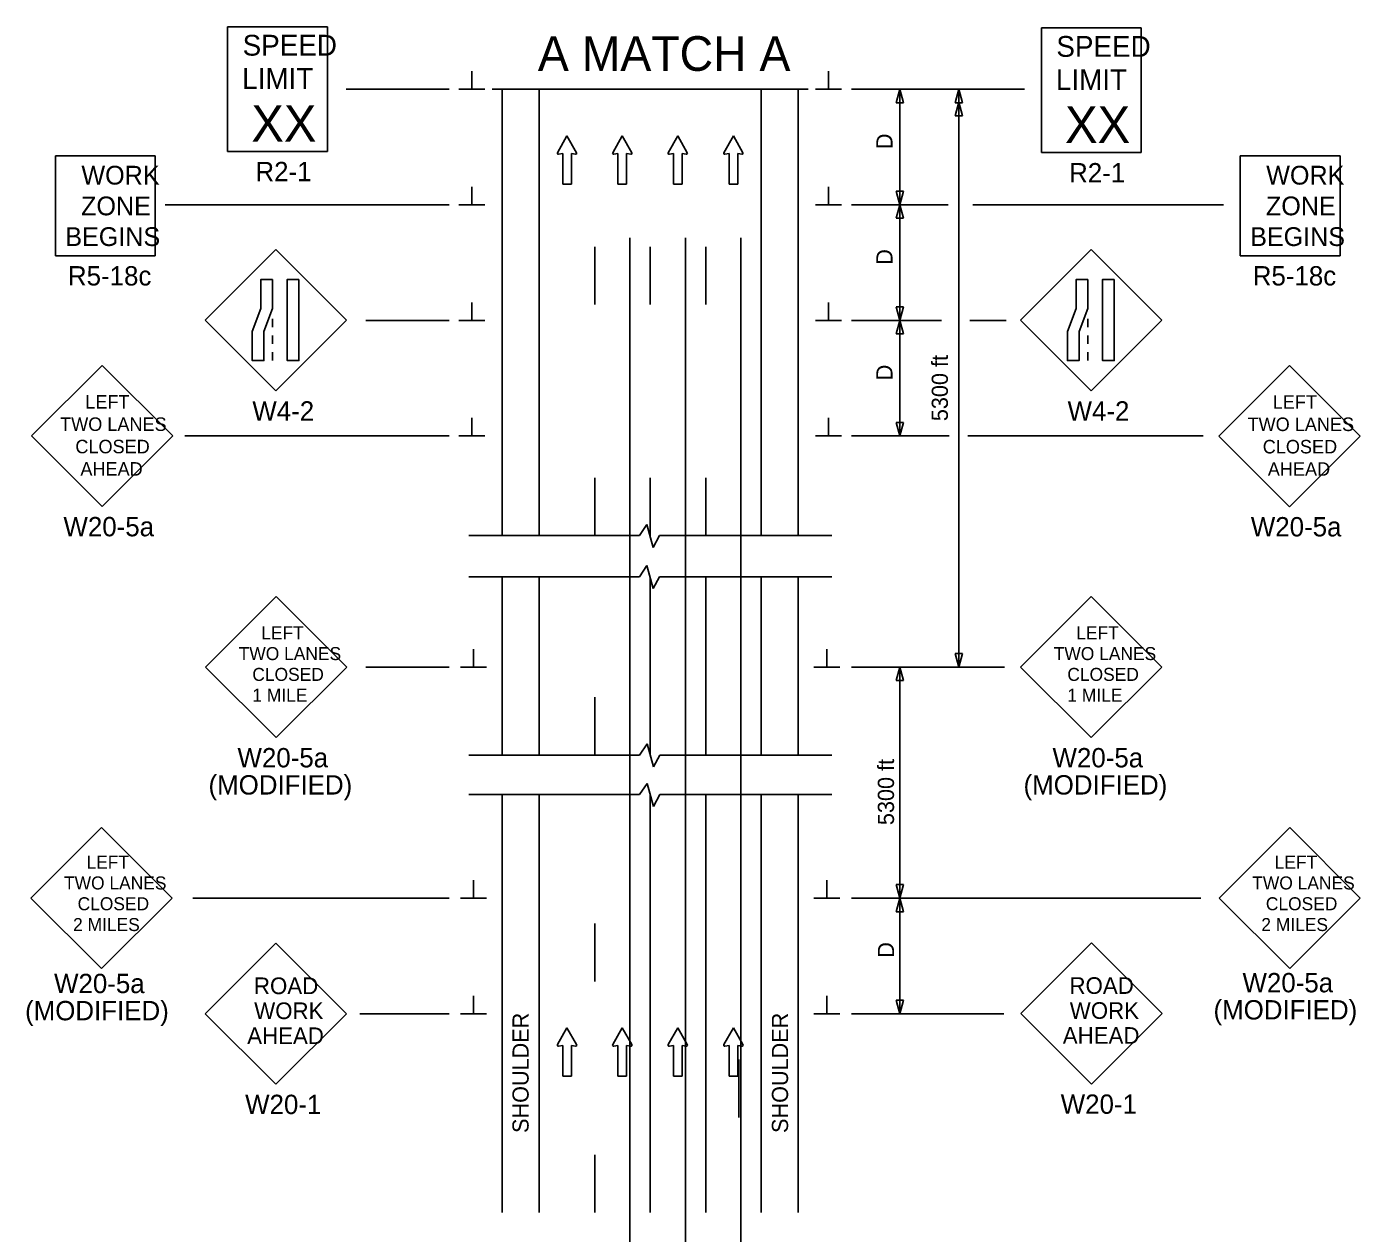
# Model space of a CAD drawing. Extents: x 16715 to 19504, y 7040 to 8495.
# Drawn here: x 17815 to 18392, y 7680 to 8202 of the extents above; entities that cross this region are included whole.
import ezdxf

# ---------------------------------------------------------------- set-up
doc = ezdxf.new("R2010")
doc.units = 0
for name, color, linetype in [('ALI_LEGAL_EX', 7, 'Continuous'), ('MT_SCRATCH_LEVEL_E', 7, 'Continuous'), ('PAVT_EDGE_EX', 7, 'Continuous'), ('TRAFFIC_SIGNS_PR', 7, 'Continuous'), ('TYPICAL_TEXT_DIMEN_PR', 7, 'Continuous')]:
    doc.layers.add(name, color=color, linetype=linetype)

msp = doc.modelspace()

# ---------------------------------------------------------------- linework, layer by layer
at = {"layer": 'ALI_LEGAL_EX'}
for p, q in [((18076.31, 7500.83), (18076.31, 8111.03)), ((18100.31, 7500.83), (18100.31, 8111.03)), ((18124.31, 7500.83), (18124.31, 8111.03)), ((18085.1, 7887.3), (18085.1, 7964.46)), ((18109.1, 7887.3), (18109.1, 7964.46)), ((18085.1, 7689.36), (18085.1, 7870.16)), ((18109.1, 7689.36), (18109.1, 7870.16))]:
    msp.add_line(p, q, dxfattribs=at)
for points in [[(18061.1, 8082.21), (18061.1, 8107.21)], [(18085.1, 8082.21), (18085.1, 8107.21)], [(18109.1, 8082.21), (18109.1, 8107.21)], [(18061.1, 7982.2), (18061.1, 8007.21)], [(18085.1, 7981.86), (18085.1, 8007.21)], [(18109.1, 7982.2), (18109.1, 8007.21)], [(18061.1, 7887.29), (18061.1, 7912.3)], [(18085.1, 7887.27), (18085.1, 7912.3)], [(18109.1, 7887.29), (18109.1, 7912.3)], [(18061.1, 7789.36), (18061.1, 7814.36)], [(18085.1, 7789.36), (18085.1, 7814.36)], [(18109.1, 7789.36), (18109.1, 7814.36)], [(18123.44, 7755.49), (18123.44, 7730.49)], [(18061.1, 7689.36), (18061.1, 7714.36)], [(18085.1, 7689.36), (18085.1, 7714.36)], [(18109.1, 7689.36), (18109.1, 7714.36)]]:
    msp.add_lwpolyline(points, dxfattribs=at)
at = {"layer": 'MT_SCRATCH_LEVEL_E'}
for p, q in [((18049.1, 8155.12), (18044.99, 8147.88)), ((18053.25, 8147.88), (18049.1, 8155.12)), ((18073.01, 8155.12), (18068.9, 8147.88)), ((18077.15, 8147.88), (18073.01, 8155.12)), ((18097.01, 8155.12), (18092.9, 8147.88)), ((18101.15, 8147.88), (18097.01, 8155.12)), ((18121.06, 8155.12), (18116.95, 8147.88)), ((18125.21, 8147.88), (18121.06, 8155.12)), ((18045.47, 8147.19), (18047.25, 8147.51)), ((18047.25, 8147.51), (18047.25, 8134.25)), ((18050.99, 8134.25), (18050.99, 8147.51)), ((18050.99, 8147.51), (18052.77, 8147.19)), ((18069.38, 8147.19), (18071.15, 8147.51)), ((18071.15, 8147.51), (18071.15, 8134.25)), ((18074.9, 8134.25), (18074.9, 8147.51)), ((18074.9, 8147.51), (18076.67, 8147.19)), ((18093.38, 8147.19), (18095.15, 8147.51)), ((18095.15, 8147.51), (18095.15, 8134.25)), ((18098.9, 8134.25), (18098.9, 8147.51)), ((18098.9, 8147.51), (18100.67, 8147.19)), ((18117.43, 8147.19), (18119.21, 8147.51)), ((18119.21, 8147.51), (18119.21, 8134.25)), ((18122.95, 8134.25), (18122.95, 8147.51)), ((18122.95, 8147.51), (18124.73, 8147.19)), ((18047.25, 8134.25), (18050.99, 8134.25)), ((18071.15, 8134.25), (18074.9, 8134.25)), ((18095.15, 8134.25), (18098.9, 8134.25)), ((18119.21, 8134.25), (18122.95, 8134.25)), ((18049.1, 7769.24), (18044.99, 7761.99)), ((18053.25, 7761.99), (18049.1, 7769.24)), ((18073.01, 7769.24), (18068.9, 7761.99)), ((18077.15, 7761.99), (18073.01, 7769.24)), ((18097.01, 7769.24), (18092.9, 7761.99)), ((18101.15, 7761.99), (18097.01, 7769.24)), ((18121.06, 7769.24), (18116.95, 7761.99)), ((18125.21, 7761.99), (18121.06, 7769.24)), ((18045.47, 7761.31), (18047.25, 7761.62)), ((18047.25, 7761.62), (18047.25, 7748.37)), ((18050.99, 7748.37), (18050.99, 7761.62)), ((18050.99, 7761.62), (18052.77, 7761.31)), ((18069.38, 7761.31), (18071.15, 7761.62)), ((18071.15, 7761.62), (18071.15, 7748.37)), ((18074.9, 7748.37), (18074.9, 7761.62)), ((18074.9, 7761.62), (18076.67, 7761.31)), ((18093.38, 7761.31), (18095.15, 7761.62)), ((18095.15, 7761.62), (18095.15, 7748.37)), ((18098.9, 7748.37), (18098.9, 7761.62)), ((18098.9, 7761.62), (18100.67, 7761.31)), ((18117.43, 7761.31), (18119.21, 7761.62)), ((18119.21, 7761.62), (18119.21, 7748.37)), ((18122.95, 7748.37), (18122.95, 7761.62)), ((18122.95, 7761.62), (18124.73, 7761.31)), ((18047.25, 7748.37), (18050.99, 7748.37)), ((18071.15, 7748.37), (18074.9, 7748.37)), ((18095.15, 7748.37), (18098.9, 7748.37)), ((18119.21, 7748.37), (18122.95, 7748.37))]:
    msp.add_line(p, q, dxfattribs=at)
for centre, start, end in [((18045.4, 8147.65), 150.42484, 279.96381), ((18052.84, 8147.65), 260.03619, 29.77312), ((18069.3, 8147.65), 150.42484, 279.96381), ((18076.74, 8147.65), 260.03619, 29.77312), ((18093.3, 8147.65), 150.42484, 279.96381), ((18100.74, 8147.65), 260.03619, 29.77312), ((18117.36, 8147.65), 150.42484, 279.96381), ((18124.8, 8147.65), 260.03619, 29.77312), ((18045.4, 7761.77), 150.42484, 279.96381), ((18052.84, 7761.77), 260.03619, 29.77312), ((18069.3, 7761.77), 150.42484, 279.96381), ((18076.74, 7761.77), 260.03619, 29.77312), ((18093.3, 7761.77), 150.42484, 279.96381), ((18100.74, 7761.77), 260.03619, 29.77312), ((18117.36, 7761.77), 150.42484, 279.96381), ((18124.8, 7761.77), 260.03619, 29.77312)]:
    msp.add_arc(centre, 0.463, start, end, dxfattribs=at)
at = {"layer": 'PAVT_EDGE_EX'}
for p, q in [((18021.1, 8175.36), (18021.1, 7982.2)), ((18037.1, 8175.36), (18037.1, 7982.2)), ((18133.1, 8175.36), (18133.1, 7982.2)), ((18149.1, 8175.36), (18149.1, 7982.2)), ((18021.1, 7964.45), (18021.1, 7887.29)), ((18037.1, 7964.46), (18037.1, 7887.29)), ((18133.1, 7964.45), (18133.1, 7887.29)), ((18149.1, 7964.45), (18149.1, 7887.29)), ((18021.1, 7870.15), (18021.1, 7689.36)), ((18037.1, 7870.15), (18037.1, 7689.36)), ((18133.1, 7870.15), (18133.1, 7689.36)), ((18149.1, 7870.15), (18149.1, 7689.36))]:
    msp.add_line(p, q, dxfattribs=at)
at = {"layer": 'TRAFFIC_SIGNS_PR'}
for p, q in [((17902.34, 8202.42), (17945.54, 8202.42)), ((17902.34, 8148.42), (17902.34, 8202.42)), ((17945.54, 8148.42), (17945.54, 8202.42)), ((18254.25, 8201.91), (18297.45, 8201.91)), ((18254.25, 8147.91), (18254.25, 8201.91)), ((18297.45, 8147.91), (18297.45, 8201.91)), ((17827.86, 8103.31), (17827.86, 8146.51)), ((17827.86, 8146.51), (17871.06, 8146.51)), ((17871.06, 8103.31), (17871.06, 8146.51)), ((17902.34, 8148.42), (17945.54, 8148.42)), ((18254.25, 8147.91), (18297.45, 8147.91)), ((18340.27, 8103.31), (18340.27, 8146.51)), ((18340.27, 8146.51), (18383.47, 8146.51)), ((18383.47, 8103.31), (18383.47, 8146.51)), ((17923.19, 8105.95), (17892.65, 8075.4)), ((17953.74, 8075.4), (17923.19, 8105.95)), ((18275.77, 8105.94), (18245.23, 8075.4)), ((18306.32, 8075.4), (18275.77, 8105.94)), ((17827.86, 8103.31), (17871.06, 8103.31)), ((18340.27, 8103.31), (18383.47, 8103.31)), ((17892.65, 8075.4), (17923.19, 8044.85)), ((17921.79, 8075.95), (17921.79, 8072.35)), ((17923.19, 8044.85), (17953.74, 8075.4)), ((18245.23, 8075.4), (18275.77, 8044.85)), ((18274.37, 8075.95), (18274.37, 8072.35)), ((18275.77, 8044.85), (18306.32, 8075.4)), ((17921.79, 8068.75), (17921.79, 8065.15)), ((18274.37, 8068.75), (18274.37, 8065.15)), ((17921.79, 8061.55), (17921.79, 8057.95)), ((18274.37, 8061.55), (18274.37, 8057.95)), ((17848.05, 8055.88), (17817.5, 8025.33)), ((17878.6, 8025.33), (17848.05, 8055.88)), ((18361.58, 8055.83), (18331.04, 8025.28)), ((18392.13, 8025.28), (18361.58, 8055.83)), ((17817.5, 8025.33), (17848.05, 7994.79)), ((17848.05, 7994.79), (17878.6, 8025.33)), ((18331.04, 8025.28), (18361.58, 7994.74)), ((18361.58, 7994.74), (18392.13, 8025.28)), ((17923.32, 7955.91), (17892.77, 7925.36)), ((17953.87, 7925.36), (17923.32, 7955.91)), ((18275.81, 7955.91), (18245.26, 7925.36)), ((18306.35, 7925.36), (18275.81, 7955.91)), ((17892.77, 7925.36), (17923.32, 7894.82)), ((17923.32, 7894.82), (17953.87, 7925.36)), ((18245.26, 7925.36), (18275.81, 7894.82)), ((18275.81, 7894.82), (18306.35, 7925.36)), ((17847.77, 7855.97), (17817.22, 7825.43)), ((17878.31, 7825.43), (17847.77, 7855.97)), ((18361.66, 7855.97), (18331.12, 7825.43)), ((18392.21, 7825.43), (18361.66, 7855.97)), ((17817.22, 7825.43), (17847.77, 7794.88)), ((17847.77, 7794.88), (17878.31, 7825.43)), ((18331.12, 7825.43), (18361.66, 7794.88)), ((18361.66, 7794.88), (18392.21, 7825.43)), ((17923.22, 7805.91), (17892.68, 7775.36)), ((17953.77, 7775.36), (17923.22, 7805.91)), ((18275.94, 7806.02), (18245.39, 7775.48)), ((18306.49, 7775.48), (18275.94, 7806.02)), ((17892.68, 7775.36), (17923.22, 7744.82)), ((17923.22, 7744.82), (17953.77, 7775.36)), ((18245.39, 7775.48), (18275.94, 7744.93)), ((18275.94, 7744.93), (18306.49, 7775.48))]:
    msp.add_line(p, q, dxfattribs=at)
for points in [[(17921.79, 8093.1), (17921.79, 8080.52), (17918.03, 8070.53), (17918.03, 8057.95), (17912.97, 8057.95), (17912.97, 8070.53), (17916.74, 8080.52), (17916.74, 8093.1)], [(17933.19, 8093.1), (17933.19, 8057.95), (17928.14, 8057.95), (17928.14, 8093.1)], [(18274.37, 8093.1), (18274.37, 8080.52), (18270.61, 8070.53), (18270.61, 8057.95), (18265.55, 8057.95), (18265.55, 8070.53), (18269.32, 8080.52), (18269.32, 8093.1)], [(18285.77, 8093.1), (18285.77, 8057.95), (18280.72, 8057.95), (18280.72, 8093.1)]]:
    msp.add_lwpolyline(points, close=True, dxfattribs=at)
at = {"layer": 'TYPICAL_TEXT_DIMEN_PR'}
for p, q in [((18007.98, 8175.36), (18007.98, 8183.15)), ((18007.98, 8175.36), (18007.98, 8183.15)), ((18162.23, 8175.36), (18162.23, 8183.15)), ((17953.67, 8175.36), (17994.88, 8175.36)), ((17972.1, 8175.36), (17998.1, 8175.36)), ((18002.35, 8175.36), (18013.6, 8175.36)), ((18002.35, 8175.36), (18013.6, 8175.36)), ((18016.78, 8175.36), (18153.43, 8175.36)), ((18167.85, 8175.36), (18156.6, 8175.36)), ((18209.51, 8175.36), (18172.1, 8175.36)), ((18191.53, 8169.5), (18193.1, 8175.36)), ((18193.1, 8175.36), (18193.1, 8125.36)), ((18193.1, 8175.36), (18194.67, 8169.5)), ((18246.91, 8175.36), (18209.51, 8175.36)), ((18216.97, 8169.5), (18218.54, 8175.36)), ((18218.54, 8175.36), (18218.54, 7925.36)), ((18218.54, 8175.36), (18220.11, 8169.5)), ((18193.1, 8169.5), (18191.53, 8169.5)), ((18194.67, 8169.5), (18193.1, 8169.5)), ((18216.97, 8163.84), (18218.54, 8169.7)), ((18218.54, 8169.5), (18216.97, 8169.5)), ((18218.54, 8169.7), (18220.11, 8163.84)), ((18220.11, 8169.5), (18218.54, 8169.5)), ((18218.54, 8163.84), (18216.97, 8163.84)), ((18220.11, 8163.84), (18218.54, 8163.84)), ((18007.98, 8125.36), (18007.98, 8133.15)), ((18007.98, 8125.36), (18007.98, 8133.15)), ((18007.98, 8125.36), (18007.98, 8133.15)), ((18162.23, 8125.36), (18162.23, 8133.15)), ((18162.23, 8125.36), (18162.23, 8133.15)), ((18193.1, 8125.36), (18191.53, 8131.23)), ((18191.53, 8131.23), (18193.1, 8131.23)), ((18193.1, 8131.23), (18194.67, 8131.23)), ((18194.67, 8131.23), (18193.1, 8125.36)), ((17875.35, 8125.36), (17998.1, 8125.36)), ((17972.1, 8125.36), (17998.1, 8125.36)), ((17972.1, 8125.36), (17998.1, 8125.36)), ((18002.35, 8125.36), (18013.6, 8125.36)), ((18002.35, 8125.36), (18013.6, 8125.36)), ((18002.35, 8125.36), (18013.6, 8125.36)), ((18167.85, 8125.36), (18156.6, 8125.36)), ((18167.85, 8125.36), (18156.6, 8125.36)), ((18198.1, 8125.36), (18172.1, 8125.36)), ((18213.9, 8125.36), (18172.1, 8125.36)), ((18191.53, 8119.5), (18193.1, 8125.36)), ((18191.53, 8119.5), (18193.1, 8125.36)), ((18193.1, 8125.36), (18193.1, 8075.36)), ((18193.1, 8125.36), (18194.67, 8119.5)), ((18193.1, 8125.36), (18194.67, 8119.5)), ((18333.02, 8125.36), (18224.62, 8125.36)), ((18193.1, 8119.5), (18191.53, 8119.5)), ((18193.1, 8119.5), (18191.53, 8119.5)), ((18194.67, 8119.5), (18193.1, 8119.5)), ((18194.67, 8119.5), (18193.1, 8119.5)), ((18007.98, 8075.36), (18007.98, 8083.15)), ((18007.98, 8075.36), (18007.98, 8083.15)), ((18007.98, 8075.36), (18007.98, 8083.15)), ((18162.23, 8075.36), (18162.23, 8083.15)), ((18162.23, 8075.36), (18162.23, 8083.15)), ((18193.1, 8075.36), (18191.53, 8081.23)), ((18191.53, 8081.23), (18193.1, 8081.23)), ((18193.1, 8081.23), (18194.67, 8081.23)), ((18194.67, 8081.23), (18193.1, 8075.36)), ((17962.1, 8075.36), (17998.1, 8075.36)), ((17972.1, 8075.36), (17998.1, 8075.36)), ((17972.1, 8075.36), (17998.1, 8075.36)), ((18002.35, 8075.36), (18013.6, 8075.36)), ((18002.35, 8075.36), (18013.6, 8075.36)), ((18002.35, 8075.36), (18013.6, 8075.36)), ((18167.85, 8075.36), (18156.6, 8075.36)), ((18167.85, 8075.36), (18156.6, 8075.36)), ((18198.1, 8075.36), (18172.1, 8075.36)), ((18211.01, 8075.36), (18172.1, 8075.36)), ((18191.53, 8069.5), (18193.1, 8075.36)), ((18191.53, 8069.5), (18193.1, 8075.36)), ((18193.1, 8075.36), (18193.1, 8025.36)), ((18193.1, 8075.36), (18194.67, 8069.5)), ((18193.1, 8075.36), (18194.67, 8069.5)), ((18238.98, 8075.36), (18223.38, 8075.36)), ((18193.1, 8069.5), (18191.53, 8069.5)), ((18193.1, 8069.5), (18191.53, 8069.5)), ((18194.67, 8069.5), (18193.1, 8069.5)), ((18194.67, 8069.5), (18193.1, 8069.5)), ((18007.98, 8025.36), (18007.98, 8033.15)), ((18162.23, 8025.36), (18162.23, 8033.15)), ((18193.1, 8025.36), (18191.53, 8031.23)), ((18191.53, 8031.23), (18193.1, 8031.23)), ((18193.1, 8031.23), (18194.67, 8031.23)), ((18194.67, 8031.23), (18193.1, 8025.36)), ((17883.82, 8025.36), (17998.1, 8025.36)), ((18002.35, 8025.36), (18013.6, 8025.36)), ((18167.85, 8025.36), (18156.6, 8025.36)), ((18214.33, 8025.36), (18172.1, 8025.36)), ((18324.28, 8025.36), (18222.47, 8025.36)), ((18083.69, 7987), (18080.43, 7982.2)), ((18086.43, 7977.06), (18083.69, 7987)), ((18080.43, 7982.2), (18006.6, 7982.2)), ((18089.17, 7982.2), (18086.43, 7977.06)), ((18163.6, 7982.2), (18089.17, 7982.2)), ((18083.69, 7969.24), (18080.43, 7964.45)), ((18086.43, 7959.31), (18083.69, 7969.24)), ((18080.43, 7964.45), (18006.6, 7964.45)), ((18089.17, 7964.45), (18086.43, 7959.31)), ((18163.6, 7964.45), (18089.17, 7964.45)), ((18008.73, 7925.36), (18008.73, 7933.15)), ((18161.48, 7925.36), (18161.48, 7933.15)), ((18218.54, 7925.36), (18216.97, 7931.23)), ((18216.97, 7931.23), (18218.54, 7931.23)), ((18218.54, 7931.23), (18220.11, 7931.23)), ((18220.11, 7931.23), (18218.54, 7925.36)), ((17962.1, 7925.36), (17998.1, 7925.36)), ((18003.1, 7925.36), (18014.35, 7925.36)), ((18167.1, 7925.36), (18155.85, 7925.36)), ((18238.26, 7925.36), (18172.1, 7925.36)), ((18191.53, 7919.5), (18193.1, 7925.36)), ((18193.1, 7925.36), (18193.1, 7825.36)), ((18193.1, 7925.36), (18194.67, 7919.5)), ((18193.1, 7919.5), (18191.53, 7919.5)), ((18194.67, 7919.5), (18193.1, 7919.5)), ((18083.78, 7892.09), (18080.52, 7887.29)), ((18086.52, 7882.15), (18083.78, 7892.09)), ((18080.52, 7887.29), (18006.6, 7887.29)), ((18089.26, 7887.29), (18086.52, 7882.15)), ((18163.6, 7887.29), (18089.26, 7887.29)), ((18083.78, 7874.95), (18080.52, 7870.15)), ((18086.52, 7865.01), (18083.78, 7874.95)), ((18080.52, 7870.15), (18006.6, 7870.15)), ((18089.26, 7870.15), (18086.52, 7865.01)), ((18163.6, 7870.15), (18089.26, 7870.15)), ((18008.73, 7825.36), (18008.73, 7833.15)), ((18161.48, 7825.36), (18161.48, 7833.15)), ((18193.1, 7825.36), (18191.53, 7831.23)), ((18191.53, 7831.23), (18193.1, 7831.23)), ((18193.1, 7831.23), (18194.67, 7831.23)), ((18194.67, 7831.23), (18193.1, 7825.36)), ((17887.29, 7825.36), (17998.1, 7825.36)), ((18003.1, 7825.36), (18014.35, 7825.36)), ((18167.1, 7825.36), (18155.85, 7825.36)), ((18323.29, 7825.36), (18172.1, 7825.36)), ((18191.53, 7819.5), (18193.1, 7825.36)), ((18193.1, 7825.36), (18193.1, 7775.36)), ((18193.1, 7825.36), (18194.67, 7819.5)), ((18193.1, 7819.5), (18191.53, 7819.5)), ((18194.67, 7819.5), (18193.1, 7819.5)), ((18008.73, 7775.36), (18008.73, 7783.15)), ((18161.48, 7775.36), (18161.48, 7783.15)), ((18193.1, 7775.36), (18191.53, 7781.23)), ((18191.53, 7781.23), (18193.1, 7781.23)), ((18193.1, 7781.23), (18194.67, 7781.23)), ((18194.67, 7781.23), (18193.1, 7775.36)), ((17959.56, 7775.36), (17998.1, 7775.36)), ((18003.1, 7775.36), (18014.35, 7775.36)), ((18167.1, 7775.36), (18155.85, 7775.36)), ((18238.02, 7775.36), (18172.1, 7775.36))]:
    msp.add_line(p, q, dxfattribs=at)

# ---------------------------------------------------------------- texts
at = {"layer": 'TRAFFIC_SIGNS_PR'}
for s, height, p in [('SPEED', 9, (17908.82, 8189.89)), ('SPEED', 9, (18260.74, 8189.38)), ('LIMIT', 9, (17908.64, 8175.49)), ('LIMIT', 9, (18260.56, 8174.98)), ('XX', 15.785, (17912.59, 8152.65)), ('XX', 15.785, (18264.5, 8152.14)), ('WORK', 8.119, (17839.11, 8134.1)), ('R2-1', 8.37, (17914.35, 8135.55)), ('R2-1', 8.37, (18266.26, 8135.04)), ('WORK', 8.119, (18351.52, 8134.1)), ('ZONE', 8.119, (17838.97, 8120.81)), ('ZONE', 8.119, (18351.39, 8120.81)), ('BEGINS', 8.119, (17832.14, 8107.52)), ('BEGINS', 8.119, (18344.56, 8107.52)), ('R5-18c', 8.37, (17833.27, 8090.44)), ('R5-18c', 8.37, (18345.69, 8090.44)), ('LEFT', 5.85, (17840.78, 8037.18)), ('W4-2', 8.37, (17913.02, 8031.98)), ('W4-2', 8.37, (18265.6, 8031.98)), ('LEFT', 5.85, (18354.31, 8037.13)), ('TWO LANES', 5.85, (17829.89, 8027.51)), ('TWO LANES', 5.85, (18343.43, 8027.46)), ('CLOSED', 5.85, (17836.48, 8017.83)), ('CLOSED', 5.85, (18350.01, 8017.78)), ('AHEAD', 5.85, (17838.66, 8008.16)), ('AHEAD', 5.85, (18352.2, 8008.11)), ('W20-5a', 8.37, (17831.33, 7981.92)), ('W20-5a', 8.37, (18344.86, 7981.87)), ('LEFT', 5.625, (17916.85, 7937.37)), ('LEFT', 5.625, (18269.34, 7937.37)), ('TWO LANES', 5.625, (17907.13, 7928.37)), ('TWO LANES', 5.625, (18259.62, 7928.37)), ('CLOSED', 5.625, (17913.01, 7919.37)), ('CLOSED', 5.625, (18265.5, 7919.37)), ('1 MILE', 5.625, (17913, 7910.37)), ('1 MILE', 5.625, (18265.49, 7910.37)), ('W20-5a', 8.37, (17906.6, 7881.95)), ('W20-5a', 8.37, (18259.09, 7881.95)), ('(MODIFIED)', 8.37, (17894.06, 7870.2)), ('(MODIFIED)', 8.37, (18246.55, 7870.2)), ('LEFT', 5.625, (17841.3, 7838.12)), ('LEFT', 5.625, (18355.19, 7838.12)), ('TWO LANES', 5.625, (17831.58, 7829.13)), ('TWO LANES', 5.625, (18345.47, 7829.13)), ('CLOSED', 5.625, (17837.45, 7820.13)), ('CLOSED', 5.625, (18351.35, 7820.13)), ('2 MILES', 5.625, (17835.49, 7811.13)), ('2 MILES', 5.625, (18349.38, 7811.13)), ('W20-5a', 8.37, (17827.27, 7784.27)), ('W20-5a', 8.37, (18341.25, 7784.62)), ('ROAD', 7.2, (17913.71, 7783.84)), ('ROAD', 7.2, (18266.42, 7783.95)), ('(MODIFIED)', 8.37, (17814.73, 7772.52)), ('(MODIFIED)', 8.37, (18328.71, 7772.87)), ('WORK', 7.2, (17913.83, 7773.04)), ('WORK', 7.2, (18266.54, 7773.15)), ('AHEAD', 7.2, (17910.8, 7762.24)), ('AHEAD', 7.2, (18263.52, 7762.35)), ('W20-1', 8.37, (18262.63, 7732.06)), ('W20-1', 8.37, (17909.91, 7731.95))]:
    msp.add_text(s, height=height, dxfattribs=at).set_placement(p)
at = {"layer": 'TYPICAL_TEXT_DIMEN_PR'}
msp.add_text('A MATCH A', height=15, dxfattribs=at).set_placement((18036.52, 8183.3))
for s, p in [('D', (18189.9, 8149.42)), ('D', (18189.9, 8099.42)), ('5300 ft', (18213.84, 8031.74)), ('D', (18189.9, 8049.42)), ('5300 ft', (18190.54, 7856.97)), ('D', (18190.54, 7799.58)), ('SHOULDER', (18032.52, 7723.78)), ('SHOULDER', (18144.72, 7723.78))]:
    msp.add_text(s, height=7, rotation=90, dxfattribs=at).set_placement(p)

doc.saveas('drawing.dxf')
